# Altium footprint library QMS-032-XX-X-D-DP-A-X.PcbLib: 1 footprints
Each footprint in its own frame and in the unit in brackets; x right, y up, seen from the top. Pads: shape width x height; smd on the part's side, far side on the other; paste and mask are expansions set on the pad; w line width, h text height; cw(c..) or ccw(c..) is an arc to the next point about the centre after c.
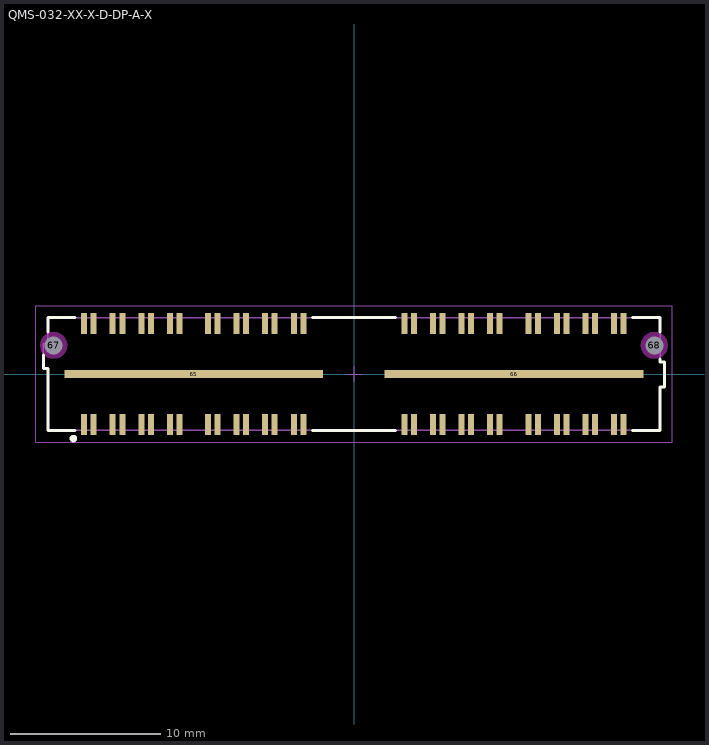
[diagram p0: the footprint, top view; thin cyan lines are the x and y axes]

## QMS-032-XX-X-D-DP-A-X [mm] "0.635mm pitch, 64 pin, rugged high speed terminal; differential"
height 5.38
pads (68):
  rect 0.4x1.4 smd mask+0: 1(-17.981,-3.365) 2(-17.981,3.365) 3(-17.346,-3.365) 4(-17.346,3.365) 5(-16.076,-3.365) 6(-16.076,3.365) 7(-15.441,-3.365) 8(-15.441,3.365) 9(-14.171,-3.365) 10(-14.171,3.365) 11(-13.536,-3.365) 12(-13.536,3.365) 13(-12.266,-3.365) 14(-12.266,3.365) 15(-11.631,-3.365) 16(-11.631,3.365) 17(-9.726,-3.365) 18(-9.726,3.365) 19(-9.091,-3.365) 20(-9.091,3.365) 21(-7.821,-3.365) 22(-7.821,3.365) 23(-7.186,-3.365) 24(-7.186,3.365) 25(-5.916,-3.365) 26(-5.916,3.365) 27(-5.281,-3.365) 28(-5.281,3.365) 29(-4.011,-3.365) 30(-4.011,3.365) 31(-3.376,-3.365) 32(-3.376,3.365) 33(17.964,3.365) 34(17.964,-3.365) 35(17.329,-3.365) 36(17.329,3.365) 37(16.059,3.365) 38(16.059,-3.365) 39(15.424,3.365) 40(15.424,-3.365) 41(14.154,3.365) 42(14.154,-3.365) 43(13.519,3.365) 44(13.519,-3.365) 45(12.249,-3.365) 46(12.249,3.365) 47(11.614,3.365) 48(11.614,-3.365) 49(9.709,3.365) 50(9.709,-3.365) 51(9.074,-3.365) 52(9.074,3.365) 53(7.804,3.365) 54(7.804,-3.365) 55(7.169,-3.365) 56(7.169,3.365) 57(5.899,3.365) 58(5.899,-3.365) 59(5.264,-3.365) 60(5.264,3.365) 61(3.994,3.365) 62(3.994,-3.365) 63(3.359,-3.365) 64(3.359,3.365)
  rect 17.25x0.5 smd mask+0: 65(-10.676,0) 66(10.664,0)
  round 1 hole 1.2 unplated mask+0: 67(-20.011,1.91) 68(20.011,1.91)
Top Overlay:
  circle w0.25: c-18.7,-4.3 r0.125
  lines w0.2: -20.7,1.25 -20.7,0.35 -20.4,0.35 -20.4,-3.75 -18.6,-3.75 ; -20.4,2.8 -20.4,3.75 -18.6,3.75 ; -2.75,-3.75 2.75,-3.75 ; -2.75,3.75 2.75,3.75 ; 18.55,-3.75 20.4,-3.75 20.4,-0.85 20.7,-0.85 20.7,0.8 20.4,0.8 20.4,1 ; 18.55,3.75 20.4,3.75 20.4,2.8
Keep-Out Layer:
  pour cut-out: -19.103,1.91 -19.134,2.145 -19.225,2.364 -19.369,2.552 -19.557,2.696 -19.776,2.787 -20.011,2.818 -20.246,2.787 -20.465,2.696 -20.653,2.552 -20.797,2.364 -20.888,2.145 -20.919,1.91 -20.888,1.675 -20.797,1.456 -20.653,1.268 -20.465,1.124 -20.246,1.033 -20.011,1.002 -19.776,1.033 -19.557,1.124 -19.369,1.268 -19.225,1.456 -19.134,1.675
  pour cut-out: 20.919,1.91 20.888,2.145 20.797,2.364 20.653,2.552 20.465,2.696 20.246,2.787 20.011,2.818 19.776,2.787 19.557,2.696 19.369,2.552 19.225,2.364 19.134,2.145 19.103,1.91 19.134,1.675 19.225,1.456 19.369,1.268 19.557,1.124 19.776,1.033 20.011,1.002 20.246,1.033 20.465,1.124 20.653,1.268 20.797,1.456 20.888,1.675
Mechanical 12:
  lines w0.001: -20.7,0.35 -20.4,0.35 -20.4,-3.75 20.4,-3.75 20.4,-0.85 20.7,-0.85 20.7,0.8 20.4,0.8 20.4,3.75 -20.4,3.75 -20.4,2 -20.7,2 -20.7,0.35
Mechanical 13:
  lines w0.1: -20.7,0.35 -20.4,0.35 -20.4,-3.75 20.4,-3.75 20.4,-0.85 20.7,-0.85 20.7,0.8 20.4,0.8 20.4,3.75 -20.4,3.75 -20.4,2 -20.7,2 -20.7,0.35
  text ".Designator" at 0.254,0.254 h1.52
Mechanical 15:
  lines w0.05: -0.5,0 0.5,0 ; 0,-0.5 0,0.5 ; -21.2,-4.55 21.2,-4.55 21.2,4.55 -21.2,4.55 -21.2,-4.55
